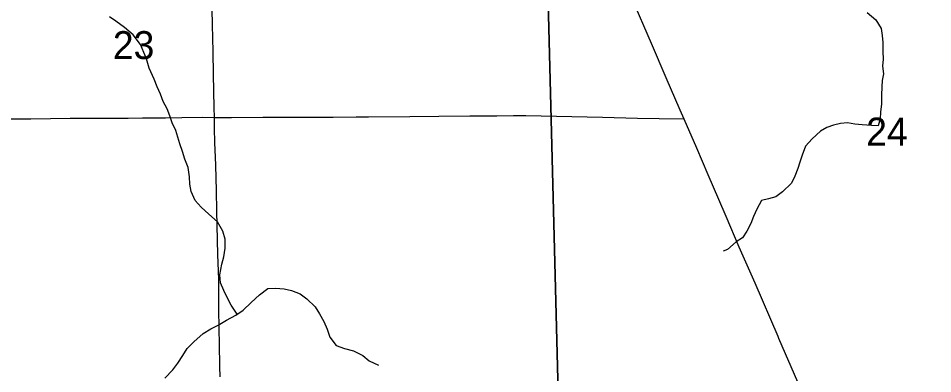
# Model space of a CAD drawing. Extents: x 1874609 to 2204689, y 815661 to 1281160.
# Drawn here: x 2003233 to 2010478, y 1068435 to 1071250 of the extents above; entities that cross this region are included whole.
import ezdxf

# ---------------------------------------------------------------- set-up
doc = ezdxf.new("R2010")
doc.units = 0
for name, color, linetype in [('GM_X_Minor_River', 7, 'Continuous'), ('GM_X_Section', 7, 'Continuous'), ('GM_X_Section_Text', 7, 'Continuous'), ('GM_X_Township_Road', 7, 'Continuous'), ('GM_X_US_Route', 7, 'Continuous')]:
    doc.layers.add(name, color=color, linetype=linetype)

msp = doc.modelspace()

# ---------------------------------------------------------------- linework, layer by layer
at = {"layer": 'GM_X_Minor_River'}
for points in [[(2004967.9, 1068906.1), (2004920.3, 1068976.5), (2004893.8, 1069028.4), (2004861.2, 1069094.4), (2004834.6, 1069154.4), (2004830.1, 1069218.6), (2004845.4, 1069303), (2004861, 1069359.3), (2004872.4, 1069429.6), (2004871.9, 1069499.8), (2004853.3, 1069563.9), (2004812.5, 1069637.9), (2004741.8, 1069699.5), (2004681.2, 1069753.3), (2004634.6, 1069807.1), (2004602, 1069877.1), (2004591.4, 1069935.2), (2004588.9, 1069995.4), (2004578.3, 1070067.5), (2004553.7, 1070133.6), (2004533.1, 1070193.6), (2004512.6, 1070255.7), (2004498.1, 1070307.7), (2004481.6, 1070359.8), (2004453, 1070421.8), (2004434.5, 1070477.8), (2004412, 1070531.8), (2004381.4, 1070589.8), (2004358.9, 1070649.8), (2004332.3, 1070707.8), (2004309.8, 1070767.9), (2004270.9, 1070853.9), (2004250.3, 1070928), (2004227.8, 1070980), (2004201.2, 1071042), (2004142.4, 1071119.8), (2004075.7, 1071175.5), (2004007.1, 1071227.1), (2003956.6, 1071260.9)], [(2009959.1, 1071296.7), (2010026.9, 1071238.1), (2010068.6, 1071169.6), (2010076.4, 1071113.3), (2010082.1, 1071057.1), (2010081.7, 1070986.9), (2010085.4, 1070926.7), (2010081.1, 1070870.6), (2010086.8, 1070810.3), (2010078.5, 1070756.2), (2010074.2, 1070706.1), (2010071.9, 1070641.9), (2010071.5, 1070571.7), (2010065.1, 1070507.5), (2010060.8, 1070453.4), (2010044.5, 1070399.3), (2009992.5, 1070401.6), (2009918.4, 1070406.1), (2009860.3, 1070412.5), (2009802.2, 1070422.9), (2009748.1, 1070415.3), (2009691.9, 1070403.6), (2009639.8, 1070385.9), (2009587.5, 1070356.1), (2009523.1, 1070296.3), (2009470.7, 1070236.5), (2009444.3, 1070166.4), (2009425.9, 1070110.4), (2009409.7, 1070060.3), (2009385.3, 1069998.3), (2009358.9, 1069944.3), (2009286.5, 1069874.6), (2009234.2, 1069836.8), (2009176, 1069821.1), (2009121.8, 1069807.4), (2009083.4, 1069737.4), (2009059, 1069679.4), (2009036.7, 1069623.4), (2009006.3, 1069563.4), (2008970, 1069511.4), (2008919.7, 1069479.7), (2008851.3, 1069419.9), (2008817.2, 1069406.1)], [(2004395.5, 1068400.6), (2004457.2, 1068465.3), (2004496.8, 1068517.8), (2004536.4, 1068580.3), (2004572.1, 1068634.7), (2004623.8, 1068687.3), (2004697.5, 1068754.1), (2004759.4, 1068790.6), (2004817.3, 1068819.2), (2004883.2, 1068859.8), (2004957.1, 1068898.5), (2005014.9, 1068939), (2005078.6, 1068997.7), (2005144.3, 1069060.4), (2005210.1, 1069109.1), (2005270.2, 1069113.5), (2005340.5, 1069106), (2005398.8, 1069094.4), (2005467.2, 1069066.8), (2005519.7, 1069029.1), (2005584.4, 1068965.3), (2005618.9, 1068909.4), (2005653.5, 1068847.5), (2005680.1, 1068787.5), (2005702.7, 1068725.4), (2005751.4, 1068657.6), (2005817.8, 1068634), (2005890.1, 1068616.4), (2005962.7, 1068578.9), (2006013.2, 1068537.1), (2006085.7, 1068503.5)]]:
    msp.add_lwpolyline(points, dxfattribs=at)
at = {"layer": 'GM_X_Section'}
for points in [[(2002074.9, 1073163.8), (2007385.1, 1073128.9), (2007522.5, 1067772.3), (2002208.8, 1067736.9)], [(2012766.5, 1072976.2), (2012766.6, 1072920.2), (2012811.7, 1067655.4), (2011337.2, 1067789), (2010105.8, 1067848.3), (2008728.9, 1067827.5), (2007522.5, 1067772.3), (2007385.1, 1073128.9)]]:
    msp.add_lwpolyline(points, close=True, dxfattribs=at)
at = {"layer": 'GM_X_Township_Road'}
for points in [[(2004787.3, 1070465.3), (2004785.8, 1070542.5), (2004779.5, 1070804.9), (2004776, 1070985.4), (2004772.7, 1071198.7), (2004767.6, 1071444.8), (2004763.9, 1071625.4), (2004756.9, 1071887.9), (2004752.9, 1072084.7), (2004748.4, 1072298), (2004748.8, 1072429.3), (2004746.2, 1072560.6), (2004740.4, 1072888.8), (2004732, 1073249.8), (2004728.2, 1073430.2), (2004723.3, 1073643.6), (2004720.4, 1073791.2), (2004716.2, 1073955.3), (2004713.8, 1074070), (2004712.1, 1074201), (2004708.5, 1074348.4), (2004708.1, 1074370.8)], [(2003167.4, 1070452.6), (2003331.5, 1070453), (2003643.3, 1070457.9), (2003758.1, 1070458.1), (2003873.1, 1070458.6), (2004102.9, 1070460), (2004217.8, 1070460.2), (2004398.4, 1070461.9), (2004529.7, 1070463.9), (2004693.9, 1070465.5), (2004787.3, 1070465.3)], [(2004787.3, 1070465.3), (2004792.3, 1070465.3), (2004923.7, 1070465.2), (2005170, 1070466.1), (2005416.4, 1070466.7), (2005596.9, 1070465.7), (2005728.3, 1070466.3), (2005908.8, 1070469.6), (2006007.2, 1070470.4), (2006335.6, 1070472.7), (2006565.4, 1070474.8), (2006811.5, 1070476.9), (2007024.9, 1070478.3), (2007156.1, 1070479.4), (2007254.5, 1070479), (2007861, 1070465.9), (2008139.8, 1070458.6), (2008310.5, 1070455.8), (2008505.9, 1070452.7)], [(2004832.2, 1068410.3), (2004831.1, 1068492.4), (2004827.1, 1068672.7), (2004825.9, 1068787.6), (2004821.4, 1068951.7), (2004821.1, 1069099.2), (2004821.8, 1069181.4), (2004815.4, 1069378.2), (2004809.7, 1069607.9), (2004807, 1069722.6), (2004802.4, 1069886.7), (2004797.1, 1070083.4), (2004795, 1070148.9), (2004791.3, 1070263.7), (2004789, 1070378.5), (2004787.3, 1070465.3)]]:
    msp.add_lwpolyline(points, dxfattribs=at)
at = {"layer": 'GM_X_US_Route'}
for points in [[(2008064.7, 1071473.8), (2008090.7, 1071413.7), (2008246.6, 1071052), (2008363, 1070780.4), (2008474.5, 1070524.6), (2008505.9, 1070452.7), (2008605.8, 1070223.8), (2008697.2, 1070013), (2008781.4, 1069817), (2008839.9, 1069681.4), (2008942.9, 1069439.8), (2009067.8, 1069154), (2009249.7, 1068732), (2009256.5, 1068716.3)], [(2009256.5, 1068716.3), (2009406.3, 1068370.6), (2009498.1, 1068160), (2009568.7, 1067993.8), (2009570.9, 1067988.8)]]:
    msp.add_lwpolyline(points, dxfattribs=at)

# ---------------------------------------------------------------- texts
at = {"layer": 'GM_X_Section_Text'}
for s, p in [('23', (2003982.4, 1070926.8)), ('24', (2009951, 1070242))]:
    msp.add_text(s, height=221, rotation=0.00001, dxfattribs=at).set_placement(p)

doc.saveas('drawing.dxf')
